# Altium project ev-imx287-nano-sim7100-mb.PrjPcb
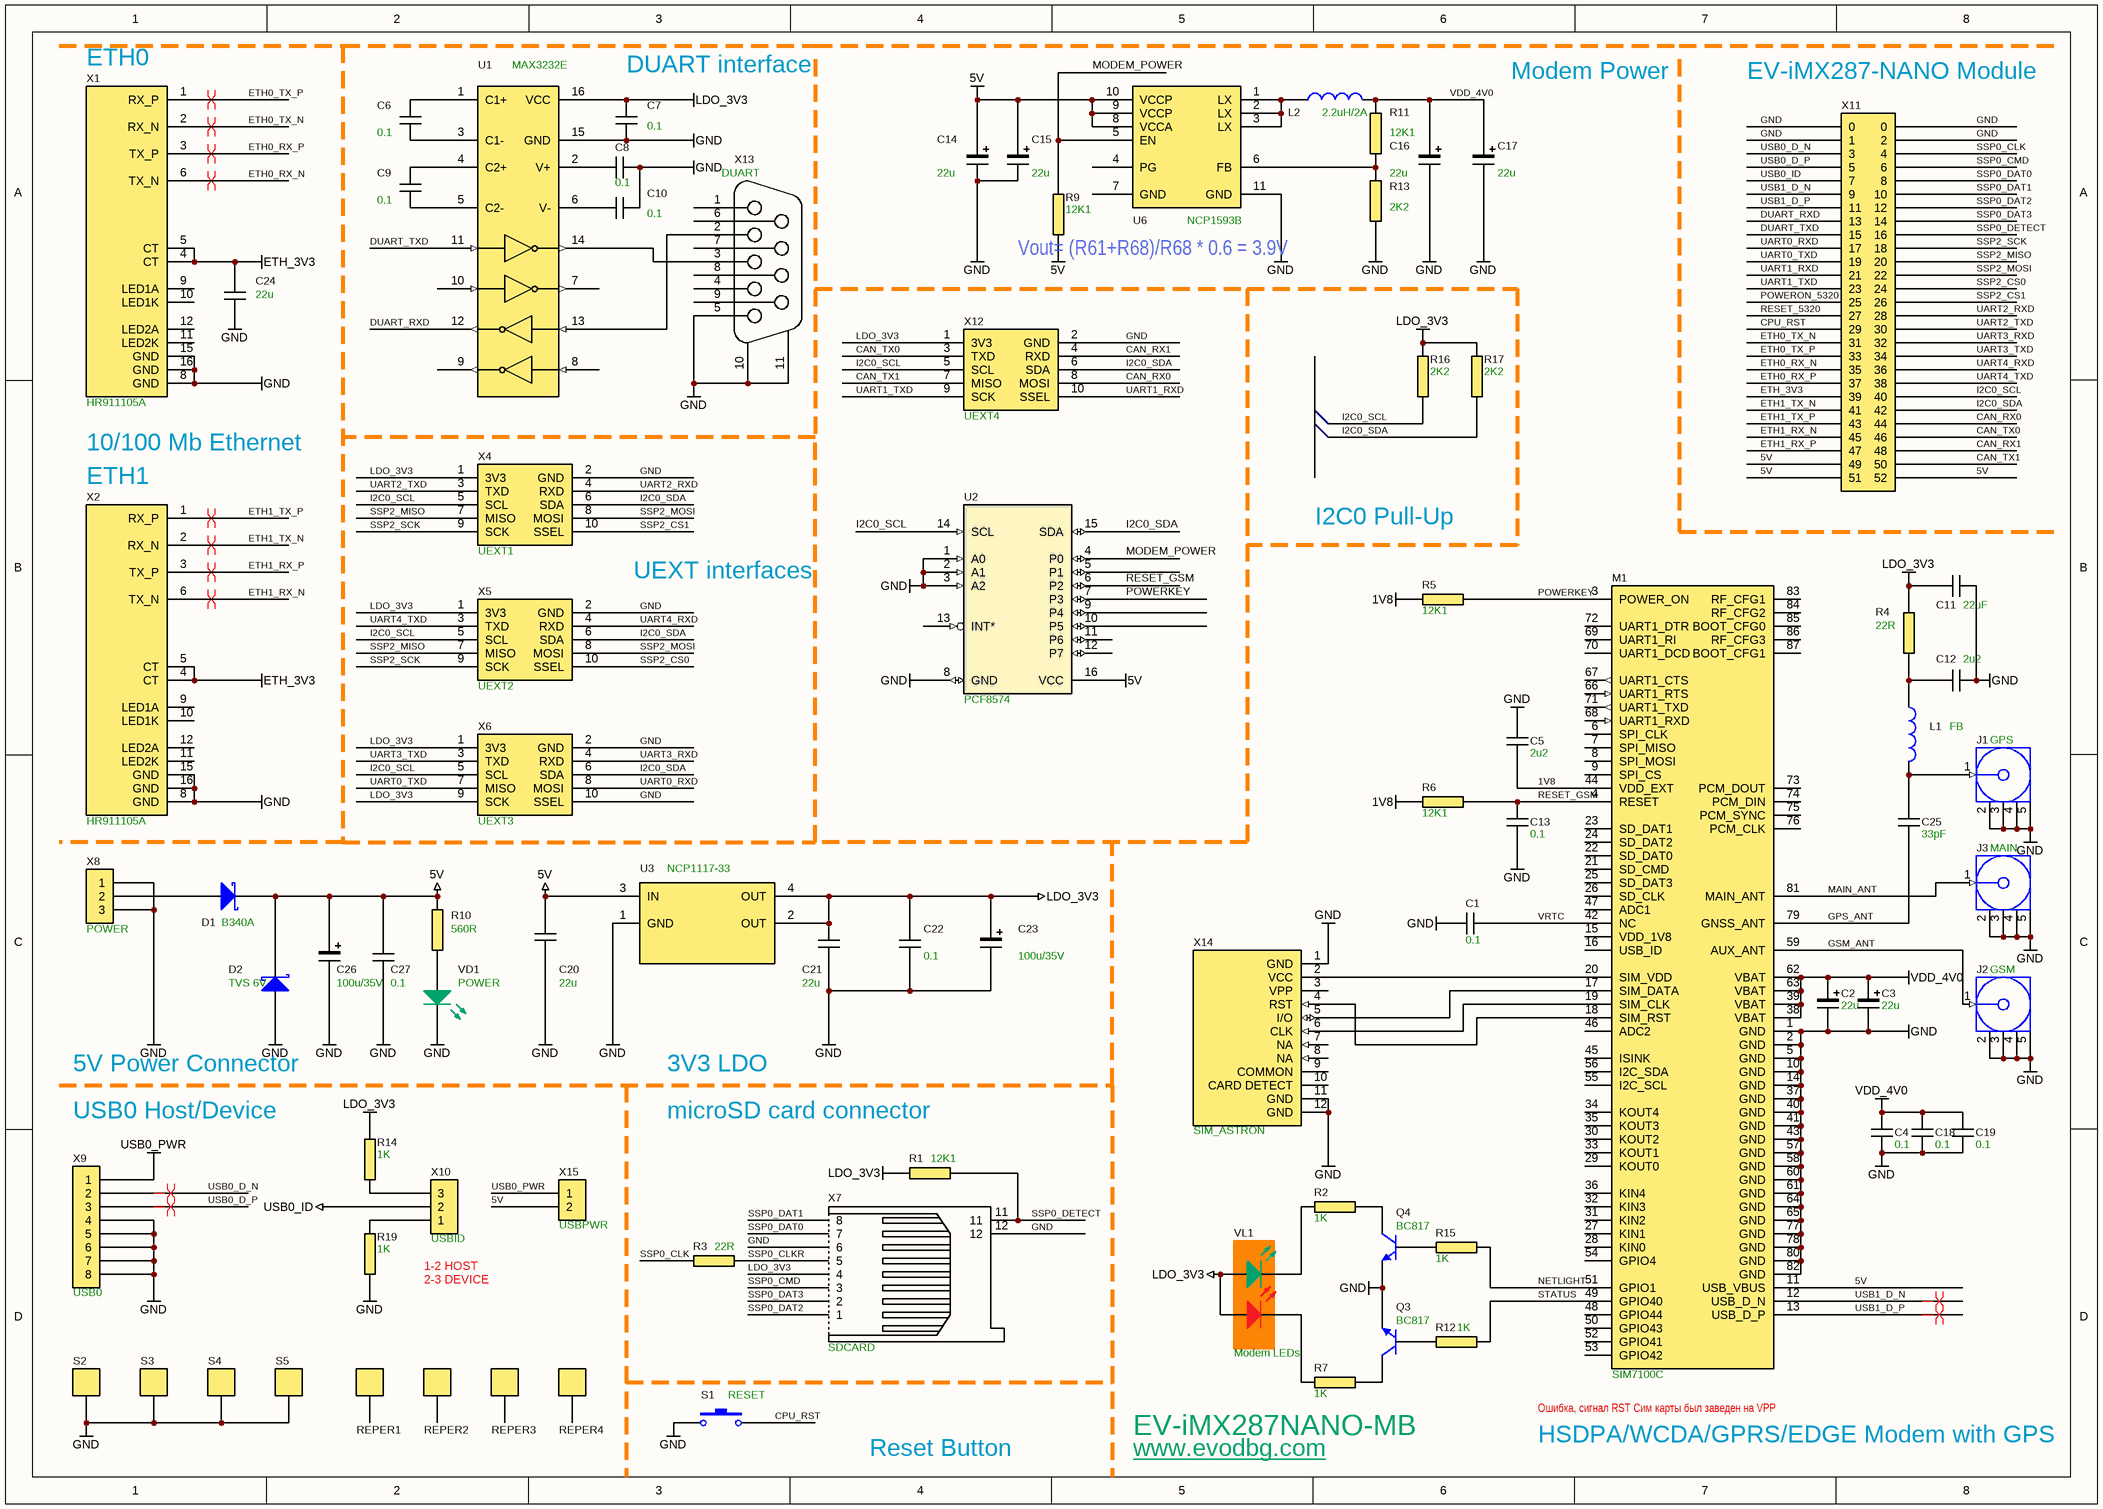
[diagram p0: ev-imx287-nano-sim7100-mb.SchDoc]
1 sheet, 83 parts. Net scope: global (net labels, ports and power ports of the same name join across sheets).
Board file: ev-imx287-nano-sim7100-mb.PcbDoc

## Sheet ev-imx287-nano-sim7100-mb.SchDoc
size A3; PageSetup: Record=PageOptions¦CenterHorizontal=True¦CenterVertical=True¦PrintScale=0.73¦XCorrection=1.00¦YCorrection=1.00¦PrintKind=0¦BorderSize=5000000¦LeftOffset=0¦BottomOffset=0¦Orientation=2¦PaperLength=1000¦PaperWidth=1000¦Scale=100¦PaperSource=7¦PrintQuality=-4¦MediaType=1¦DitherType=10¦PrintScaleMode=1¦PaperKind=A4¦PaperIndex=9

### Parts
C1  0.1  [IPC_C0603]
C2  22u  [IPC_C0805]
C3  22u  [IPC_C0805]
C4  0.1  [IPC_C0603]
C5  2u2  [IPC_C0603]
C6  0.1  [IPC_C0603]
C7  0.1  [IPC_C0603]
C8  0.1  [IPC_C0603]
C9  0.1  [IPC_C0603]
C10  0.1  [IPC_C0603]
C11  22uF  [IPC_C0805]
C12  2u2  [IPC_C0603]
C13  0.1  [IPC_C0603]
C14  22u  [ipc_c0805]
C15  22u  [ipc_c0805]
C16  22u  [IPC_C0805]
C17  22u  [IPC_C0805]
C18  0.1  [IPC_C0603]
C19  0.1  [IPC_C0603]
C20  22u  [IPC_C0805]
C21  22u  [IPC_C0805]
C22  0.1  [IPC_C0603]
C23  100u/35V  [ALU_SMD_5.3]
C24  22u  [IPC_C0805]
C25  33pF  [IPC_C0603]
C26  100u/35V  [ALU_SMD_5.3]
C27  0.1  [IPC_C0603]
D1  B340A  [SMA]
D2  TVS 6V  [SMA]
J1  GPS  [SMA_RF]
J2  GSM  [SMA_RF]
J3  MAIN  [SMA_RF]
L1  FB  [L0603]
L2  2.2uH/2A  [VLCF4020]
M1  SIM7100C  [SIM7100C]
Q3  BC817  [SOT23]
Q4  BC817  [SOT23]
R1  12K1  [IPC_R0603]
R2  1K  [IPC_R0603]
R3  22R  [IPC_R0603]
R4  22R  [IPC_R0603]
R5  12K1  [IPC_R0603]
R6  12K1  [IPC_R0603]
R7  1K  [IPC_R0603]
R9  12K1  [IPC_R0603]
R10  560R  [IPC_R0603]
R11  12K1  [IPC_R0603]
R12  1K  [IPC_R0603]
R13  2K2  [IPC_R0603]
R14  1K  [IPC_R0603]
R15  1K  [IPC_R0603]
R16  2K2  [IPC_R0603]
R17  2K2  [IPC_R0603]
R19  1K  [IPC_R0603]
REPER1  SIP1  [reper2]  (value not drawn)
REPER2  SIP1  [reper2]  (value not drawn)
REPER3  SIP1  [reper2]  (value not drawn)
REPER4  SIP1  [reper2]  (value not drawn)
S1  RESET  [TS-101]
S2  SIP1  [MOUNTING_HOLE_3MM]  (value not drawn)
S3  SIP1  [MOUNTING_HOLE_3MM]  (value not drawn)
S4  SIP1  [MOUNTING_HOLE_3MM]  (value not drawn)
S5  SIP1  [MOUNTING_HOLE_3MM]  (value not drawn)
U1  MAX3232E  [SO-16]
U2  PCF8574  [SOL-16]
U3  NCP1117-33  [DPAK]
U6  NCP1593B  [DFN10]
VD1  POWER  [l0805]
VL1  Modem LEDs  [LED3_2F]
X1  HR911105A  [ETH3A_SMD]
X2  HR911105A  [ETH3A_SMD]
X4  UEXT1  [BH10_SMT]
X5  UEXT2  [BH10_SMT]
X6  UEXT3  [BH10_SMT]
X7  SDCARD  [mSD_TF_push]
X8  POWER  [DJK-03-SMD]
X9  USB0  [USB-AC-EDGE]
X10  USBID  [SIP3]
X11  (no value)  [PCIEXPRESS_mini]
X12  UEXT4  [BH10_SMT]
X13  DUART  [DR9P]
X14  SIM_ASTRON  [SIM_ASTRON]
X15  USBPWR  [SIP2]

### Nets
1V8: C5.1 M1.44(VDD_EXT) R5.2(R2) R6.2(R2)
5V: C14.1 C15.1 C20.2 C26.1 C27.2 D1.2(K) D2.2(K) M1.11(USB_VBUS) R9.2(R2) R10.1(R1) U2.16(VCC) U3.3(IN) U6.8(VCCA) U6.9(VCCP) U6.10(VCCP) X11.49 X11.51 X11.52 X15.2
ETH_3V3: C24.2 X1.4(CT) X1.5(CT) X2.4(CT) X2.5(CT) X11.39
GND: C1.2 C2.2 C3.2 C4.2 C5.2 C7.1 C8.2 C10.1 C11.2 C12.2 C13.2 C14.2 C15.2 C16.2 C17.2 C18.2 C19.2 C20.1 C21.1 C22.1 C23.2 C24.1 C26.2 C27.1 D2.1(A) J1.2(GND) J1.3(GND) J1.4(GND) J1.5(GND) J2.2(GND) J2.3(GND) J2.4(GND) J2.5(GND) J3.2(GND) J3.3(GND) J3.4(GND) J3.5(GND) M1.1(GND) M1.2(GND) M1.5(GND) M1.10(GND) M1.14(GND) M1.37(GND) M1.40(GND) M1.41(GND) M1.43(GND) M1.57(GND) M1.58(GND) M1.60(GND) M1.61(GND) M1.64(GND) M1.65(GND) M1.77(GND) M1.78(GND) M1.80(GND) M1.82(GND) Q3.3(E) Q4.3(E) R13.1(R1) R19.1(R1) S1.1 S2.1 S3.1 S4.1 S5.1 U1.15(GND) U2.1(A0) U2.2(A1) U2.3(A2) U2.8(GND) U3.1(GND) U6.11(GND) VD1.2(K) X1.8(GND) X1.15(GND) X1.16(GND) X2.8(GND) X2.15(GND) X2.16(GND) X4.2(GND) X5.2(GND) X6.2(GND) X6.10(SSEL) X7.6 X7.12 X8.1 X8.3 X9.4 X9.5 X9.6 X9.7 X9.8 X11.0 X11.1 X11.2 X12.2(GND) X13.5 X13.10(M1) X13.11(M2) X14.1(GND) X14.11(GND) X14.12(GND)
LDO_3V3: C7.2 C11.1 C21.2 C22.2 C23.1 R1.2(R2) R4.2(R2) R14.2(R2) R16.2(R2) R17.2(R2) U1.16(VCC) U3.2(OUT) U3.4(OUT) VL1.1(A) VL1.3(A) X4.1(3V3) X5.1(3V3) X6.1(3V3) X6.9(SCK) X7.4 X12.1(3V3)
USB0_ID: X10.2 X11.7
USB0_PWR: X9.1 X15.1
VDD_4V0: C2.1 C3.1 C4.1 C16.1 C17.1 C18.1 C19.1 L2.2 M1.38(VBAT) M1.39(VBAT) M1.62(VBAT) M1.63(VBAT) R11.2(R2)
CAN_RX0: X11.44 X12.8(MOSI)
CAN_RX1: X11.48 X12.4(RXD)
CAN_TX0: X11.46 X12.3(TXD)
CAN_TX1: X11.50 X12.7(MISO)
CPU_RST: S1.2 X11.29
DUART_RXD: U1.12 X11.13
DUART_TXD: U1.11 X11.15
ETH0_RX_N: X1.6(TX_N) X11.35
ETH0_RX_P: X1.3(TX_P) X11.37
ETH0_TX_N: X1.2(RX_N) X11.31
ETH0_TX_P: X1.1(RX_P) X11.33
ETH1_RX_N: X2.6(TX_N) X11.45
ETH1_RX_P: X2.3(TX_P) X11.47
ETH1_TX_N: X2.2(RX_N) X11.41
ETH1_TX_P: X2.1(RX_P) X11.43
GPS_ANT: C25.1 M1.79(GNSS_ANT)
GSM_ANT: J2.1(Signal) M1.59(AUX_ANT)
I2C0_SCL: R16.1(R1) U2.14(SCL) X4.5(SCL) X5.5(SCL) X6.5(SCL) X11.40 X12.5(SCL)
I2C0_SDA: R17.1(R1) U2.15(SDA) X4.6(SDA) X5.6(SDA) X6.6(SDA) X11.42 X12.6(SDA)
MAIN_ANT: J3.1(Signal) M1.81(MAIN_ANT)
MODEM_POWER: R9.1(R1) U2.4(P0) U6.5(EN)
NETLIGHT: M1.51(GPIO1) R15.1(R1)
POWERKEY: M1.3(POWER_ON) R5.1(R1) U2.7(P3)
POWERON_5320: X11.25
RESET_5320: X11.27
RESET_GSM: C13.1 M1.4(RESET) R6.1(R1) U2.6(P2)
SSP0_CLK: R3.2(R2) X11.4
SSP0_CLKR: R3.1(R1) X7.5
SSP0_CMD: X7.3 X11.6
SSP0_DAT0: X7.7 X11.8
SSP0_DAT1: X7.8 X11.10
SSP0_DAT2: X7.1 X11.12
SSP0_DAT3: X7.2 X11.14
SSP0_DETECT: R1.1(R1) X7.11 X11.16
SSP2_CS0: X5.10(SSEL) X11.24
SSP2_CS1: X4.10(SSEL) X11.26
SSP2_MISO: X4.7(MISO) X5.7(MISO) X11.20
SSP2_MOSI: X4.8(MOSI) X5.8(MOSI) X11.22
SSP2_SCK: X4.9(SCK) X5.9(SCK) X11.18
STATUS: M1.49(GPIO40) R12.2(R2)
UART0_RXD: X6.8(MOSI) X11.17
UART0_TXD: X6.7(MISO) X11.19
UART1_RXD: X11.21 X12.10(SSEL)
UART1_TXD: X11.23 X12.9(SCK)
UART2_RXD: X4.4(RXD) X11.28
UART2_TXD: X4.3(TXD) X11.30
UART3_RXD: X6.4(RXD) X11.32
UART3_TXD: X6.3(TXD) X11.34
UART4_RXD: X5.4(RXD) X11.36
UART4_TXD: X5.3(TXD) X11.38
USB0_D_N: X9.2 X11.3
USB0_D_P: X9.3 X11.5
USB1_D_N: M1.12(USB_D_N) X11.9
USB1_D_P: M1.13(USB_D_P) X11.11
VRTC: C1.1 M1.42(NC)
NetC6_1: C6.1 U1.3(C1-)
NetC6_2: C6.2 U1.1(C1+)
NetC8_1: C8.1 U1.2(V+)
NetC9_1: C9.1 U1.5(C2-)
NetC9_2: C9.2 U1.4(C2+)
NetC10_2: C10.2 U1.6(V-)
NetC12_1: C12.1 L1.1 R4.1(R1)
NetC25_2: C25.2 J1.1(Signal) L1.2
NetD1_1: D1.1(A) X8.2
NetL2_1: L2.1 U6.1(LX) U6.2(LX) U6.3(LX)
NetM1_17: M1.17(SIM_DATA) X14.5(I/O)
NetM1_18: M1.18(SIM_RST) X14.4(RST)
NetM1_19: M1.19(SIM_CLK) X14.6(CLK)
NetM1_20: M1.20(SIM_VDD) X14.2(VCC)
NetQ3_1: Q3.1(C) R7.2(R2)
NetQ3_2: Q3.2(B) R12.1(R1)
NetQ4_1: Q4.1(C) R2.1(R1)
NetQ4_2: Q4.2(B) R15.2(R2)
NetR2_2: R2.2(R2) VL1.2(K)
NetR7_1: R7.1(R1) VL1.4(K)
NetR10_2: R10.2(R2) VD1.1(A)
NetR11_1: R11.1(R1) R13.2(R2) U6.6(FB)
NetR14_1: R14.1(R1) X10.3
NetR19_2: R19.2(R2) X10.1
NetU1_13: U1.13 X13.2
NetU1_14: U1.14 X13.3

Not connected (* = marked no-connect by the designer): M1 6(SPI_CLK) 7(SPI_MISO) 8(SPI_MOSI) 9(SPI_CS) 15(VDD_1V8) 16(USB_ID) 21(SD_CMD) 22(SD_DAT0) 23(SD_DAT1) 24(SD_DAT2) 25(SD_DAT3) 26(SD_CLK) 27(KIN1) 28(KIN0) 29(KOUT0) 30(KOUT2) 31(KIN2) 32(KIN3) 33(KOUT1) 34(KOUT4) 35(KOUT3) 36(KIN4) 45(ISINK) 46(ADC2) 47(ADC1) 48(GPIO44) 50(GPIO43) 52(GPIO41) 53(GPIO42) 54(GPIO4) 55(I2C_SCL) 56(I2C_SDA) 66(UART1_RTS) 67(UART1_CTS) 68(UART1_RXD) 69(UART1_RI) 70(UART1_DCD) 71(UART1_TXD) 72(UART1_DTR) 73(PCM_DOUT) 74(PCM_DIN) 75(PCM_SYNC) 76(PCM_CLK) 83(RF_CFG1) 84(RF_CFG2) 85(BOOT_CFG0) 86(RF_CFG3) 87(BOOT_CFG1); REPER1 1; REPER2 1; REPER3 1; REPER4 1; U1 7 8 9 10; U2 5(P1) 9(P4) 10(P5) 11(P6) 12(P7) 13(INT*); U6 4(PG) 7(GND); X1 9(LED1A) 10(LED1K) 11(LED2K) 12(LED2A); X2 9(LED1A) 10(LED1K) 11(LED2K) 12(LED2A); X13 1 4 6 7 8 9; X14 3(VPP) 7(NA) 8(NA) 9(COMMON) 10(CARD_DETECT)

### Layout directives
differential pair: ETH0_RX_N, ETH0_RX_P, ETH0_TX_N, ETH0_TX_P, ETH1_RX_N, ETH1_RX_P, ETH1_TX_N, ETH1_TX_P, USB0_D_N, USB0_D_P, USB1_D_N, USB1_D_P

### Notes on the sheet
- (near X1) ETH0
- (near C7) DUART interface
- Modem Power
- (near X11) EV-iMX287-NANO Module
- (near R9) Vout= (R61+R68)/R68 * 0.6 = 3.9V
- 10/100 Mb Ethernet
- (near X2) ETH1
- UEXT interfaces
- I2C0 Pull-Up
- USB0 Host/Device
- 5V Power Connector
- (near R1) microSD card connector
- 3V3 LDO
- 1-2 HOST
- 2-3 DEVICE
- Reset Button
- (near R7) EV-iMX287NANO-MB
- www.evodbg.com
- HSDPA/WCDA/GPRS/EDGE Modem with GPS
- (near M1) Ошибка, сигнал RST Сим карты был заведен на VPP

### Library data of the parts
C1 C4 C5 C11-C13 C18 C19 C25 = c7
C2 C3 C16 = CP7: Manufacturer Price: 0,252; PartNumber: C3216X5R0J476MT; Type: C1206
C6-C10 C27 = c7: Type: C0603; In Stock: 0
C14 C15 = CP7: Manufacturer Price: 0,4; Type: C2010
C17 = CP7: Manufacturer Price: 0,0; PartNumber: C3216X5R0J476MT; Type: C1206
C20 C21 C24 = c7: Manufacturer Part Number: C0805C226M9PAC7800; Type: C1206; In Stock: 0
C22 = c7: Manufacturer Part Number: CL05A104KP5NNNC; Type: C0603; In Stock: 0
C23 C26 = CP7: Type: Aluminium capacitors; In Stock: 0
D1 D2 = D Schottky: Schottky Diode; Type: Diode SMA; In Stock: 0
J1-J3 = COAX-F: RF Coaxial PCB Connector, MCX; Thru-Hole, Right-Angle Mount Socket, Blunt Post Terminal, 50 Ohm Impedance; PCB_Layout: Complies with manufacturer's recommendation.; DrillSize: Corresponds to nominal value.
L1 L2 = Inductor: Type: Inductors
Q3 Q4 = NPN: NPN Bipolar Transistor
R1 R3 R7 R10 R14 R19 = r7: In Stock: 0
R2 R4-R6 R12 R15-R17 = r7
R9 R11 R13 = r7: Manufacturer Price: 0,0027
REPER1-REPER4 S2-S5 = SIP1: In Stock: 0
S1 = SW-PB: Switch; In Stock: 0
U1 = MAX3232E: In Stock: 0
U3 = TLV1117: In Stock: 0
VD1 = LED_GREEN: Type: LED's; In Stock: 0
VL1 = LED_3_2F
X1 X2 = HR911105
X4-X6 X12 = UEXT
X7 = uSD card socket: In Stock: 0
X8 X10 = SIP3: In Stock: 0
X9 = SIP8
X11 = SIP2x26
X13 = SUBD9_M_COUDE: In Stock: 0
X14 = SMARTCARD_CONNECTOR
X15 = SIP2: In Stock: 0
